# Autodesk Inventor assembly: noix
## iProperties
Author: Administrateur
Created: 2001-04
Part Number: noix
Document SubType Name: Assemblage
Designer: Administrateur
Control State: 0
Master: False
Checked Out: False
PropertySet Name: Design Tracking Control
Shininess: 60.0
PropertySet Name: _Private Model Information
Length Units: 11269
Angle Units: 11283
Time Units: 11279
Mass Units: 11290
Length Display Precision: 3
Angle Display Precision: 2
Compacted: False
Density: 0.0
Volumn: 0.0
Area: 0.0
PropertySet Name: Model Information
